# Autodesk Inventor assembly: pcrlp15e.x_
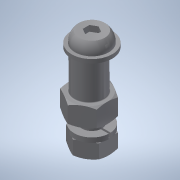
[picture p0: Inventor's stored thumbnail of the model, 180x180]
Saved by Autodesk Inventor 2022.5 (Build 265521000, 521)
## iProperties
Part Number: pcrlp15e.x_
Material: 一般
Document SubType Name: Assembly
Designer: ImaoCorp
Sending System: SOLIDWORKS 2017-2017317
MC: AMD64
MC_MODEL: Intel64 Family 6 Model 60 Stepping 3, GenuineIntel
OS: Windows_NT
FRU: Parasolid Version 29.0, build 201,  4-17-2017
FORMAT: text
GUISE: transmit
KEY: pcrlp15e
FILE: pcrlp15e.x_t
DATE: Wed Sep 04 15:35:05 2019
Author: ImaoCorp
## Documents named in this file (4)
- X:\14_SW2022-Inv2022\00_全2023-1023新製品(TCC)まで\p\pcrlp15e\PCRLP15E.iam
- X:\14_SW2022-Inv2022\00_全2023-1023新製品(TCC)まで\p\pcrlp15e\pcrlp15e_01.ipt
- X:\14_SW2022-Inv2022\00_全2023-1023新製品(TCC)まで\p\pcrlp15e\pcrlp15e_02.ipt
- X:\14_SW2022-Inv2022\00_全2023-1023新製品(TCC)まで\p\pcrlp15e\pcrlp15e_03.ipt
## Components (3 placed, 3 different names)
1. pcrlp15e_01
2. pcrlp15e_02
3. pcrlp15e_03
